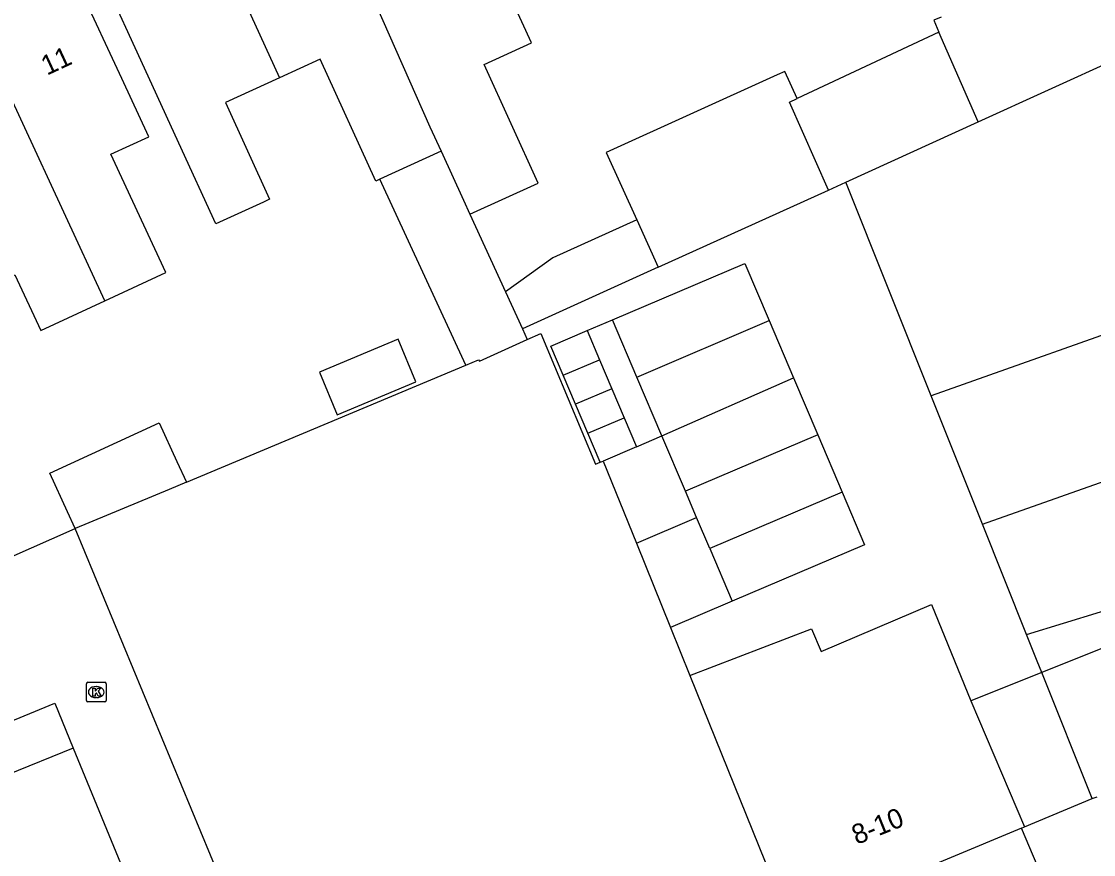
# Model space of a CAD drawing. Extents: x 160379 to 161131, y 383940 to 384849.
# Drawn here: x 161040.9 to 161095.3, y 384292.9 to 384335.2 of the extents above; entities that cross this region are included whole.
import ezdxf

# ---------------------------------------------------------------- set-up
doc = ezdxf.new("R2010")
doc.units = 0
for name, color, linetype in [('IMGEO_Kolk', 7, 'Continuous'), ('IMGEO_Muur', 7, 'Continuous'), ('IMGEO_Pand', 7, 'Continuous'), ('IMGEO_Pand_nummerreeks', 7, 'Continuous'), ('IMGEO_Pand_overbouw', 7, 'Continuous'), ('IMGEO_Voetpad_open', 7, 'Continuous')]:
    doc.layers.add(name, color=color, linetype=linetype)

msp = doc.modelspace()

# ---------------------------------------------------------------- linework, layer by layer
at = {"layer": 'IMGEO_Kolk'}
for p, q in [((161044.21, 384300.753), (161044.21, 384301.605)), ((161044.285, 384301.679), (161045.137, 384301.679)), ((161044.698, 384301.459), (161044.723, 384301.459)), ((161045.211, 384301.605), (161045.211, 384300.753)), ((161045.137, 384300.679), (161044.285, 384300.679)), ((161044.721, 384300.899), (161044.696, 384300.899))]:
    msp.add_line(p, q, dxfattribs=at)
for points in [[(161044.21, 384300.753), (161044.21, 384301.605)], [(161044.285, 384301.679), (161045.137, 384301.679)], [(161044.531, 384301.379), (161044.654, 384301.379), (161044.654, 384301.228), (161044.784, 384301.379), (161044.948, 384301.379), (161044.802, 384301.228), (161044.955, 384300.979), (161044.803, 384300.979), (161044.718, 384301.143), (161044.654, 384301.076), (161044.654, 384300.979), (161044.531, 384300.979), (161044.531, 384301.379)], [(161045.211, 384301.605), (161045.211, 384300.753)], [(161045.137, 384300.679), (161044.285, 384300.679)]]:
    msp.add_lwpolyline(points, dxfattribs=at)
for centre, start, end in [((161044.287, 384301.603), 91.552, 178.448), ((161044.287, 384301.603), 91.552, 178.448), ((161045.135, 384301.603), 1.552, 88.448), ((161045.135, 384301.603), 1.552, 88.448), ((161044.287, 384300.755), 181.552, 268.448), ((161044.287, 384300.755), 181.552, 268.448), ((161045.135, 384300.755), 271.552, 358.448), ((161045.135, 384300.755), 271.552, 358.448)]:
    msp.add_arc(centre, 0.0765, start, end, dxfattribs=at)
for centre, major_axis, ratio, start_param, end_param in [((161044.697, 384301.179), (-0.387, 0.002), 0.722429, 4.712389, 7.853982), ((161044.722, 384301.179), (-0.39, 0.002), 0.717154, 1.570796, 4.712389)]:
    msp.add_ellipse(centre, major_axis=major_axis, ratio=ratio, start_param=start_param, end_param=end_param, dxfattribs=at)
at = {"layer": 'IMGEO_Muur'}
for points in [[(161031.058, 384303.917), (161043.635, 384309.473)], [(161043.533, 384298.344), (161046.299, 384291.649)]]:
    msp.add_lwpolyline(points, dxfattribs=at)
at = {"layer": 'IMGEO_Pand'}
for points in [[(161063.67, 384325.406), (161067.13, 384326.989), (161064.382, 384332.994), (161066.784, 384334.093), (161063.869, 384340.464), (161061.789, 384345.01)], [(161056.087, 384342.401), (161061.638, 384329.845), (161062.208, 384328.6)], [(161050.558, 384339.871), (161054.008, 384332.328)], [(161054.008, 384332.328), (161051.263, 384331.072), (161053.506, 384326.171), (161053.189, 384326.026), (161050.771, 384324.923), (161048.898, 384329.016), (161047.159, 384332.817), (161045.078, 384337.363)], [(161045.14, 384321.014), (161048.232, 384322.45), (161045.449, 384328.444), (161047.376, 384329.338), (161046.004, 384332.293), (161043.899, 384336.828)], [(161087.571, 384335.404), (161087.199, 384335.247), (161087.465, 384334.636)], [(161089.448, 384330.086), (161100.161, 384334.957)], [(161045.14, 384321.014), (161038.881, 384334.499)], [(161087.465, 384334.636), (161080.266, 384331.274)], [(161089.448, 384330.086), (161087.465, 384334.636)], [(161059.102, 384327.179), (161058.895, 384327.084), (161056.065, 384333.269), (161054.008, 384332.328)], [(161080.266, 384331.274), (161079.641, 384332.65), (161079.259, 384332.477), (161070.584, 384328.541), (161072.132, 384325.129)], [(161033.861, 384332.169), (161035.966, 384327.634), (161037.783, 384323.72), (161038.808, 384321.512), (161040.584, 384322.337), (161041.897, 384319.509), (161045.14, 384321.014)], [(161081.851, 384326.634), (161079.874, 384331.091), (161080.266, 384331.274)], [(161082.731, 384327.033), (161089.448, 384330.086)], [(161062.208, 384328.6), (161059.102, 384327.179)], [(161062.208, 384328.6), (161063.341, 384326.125), (161063.67, 384325.406)], [(161063.456, 384317.756), (161059.102, 384327.179)], [(161081.851, 384326.634), (161082.731, 384327.033)], [(161087.066, 384316.202), (161082.731, 384327.033)], [(161073.225, 384322.72), (161081.851, 384326.634)], [(161063.67, 384325.406), (161065.468, 384321.479)], [(161072.132, 384325.129), (161067.868, 384323.194), (161065.468, 384321.479)], [(161072.132, 384325.129), (161073.225, 384322.72)], [(161111.312, 384324.78), (161087.066, 384316.202)], [(161073.225, 384322.72), (161066.332, 384319.592)], [(161070.9, 384320.053), (161077.616, 384322.912), (161078.85, 384320.013)], [(161065.468, 384321.479), (161066.332, 384319.592)], [(161069.611, 384319.504), (161070.9, 384320.053)], [(161072.133, 384317.154), (161070.9, 384320.053)], [(161072.133, 384317.154), (161078.85, 384320.013)], [(161078.85, 384320.013), (161080.084, 384317.115)], [(161066.332, 384319.592), (161066.575, 384319.061)], [(161066.575, 384319.061), (161067.27, 384319.352), (161070.04, 384312.733), (161070.278, 384312.832)], [(161068.398, 384317.249), (161067.771, 384318.721), (161069.611, 384319.504)], [(161069.611, 384319.504), (161070.238, 384318.032)], [(161056.035, 384317.395), (161056.938, 384315.237), (161060.928, 384316.907), (161060.025, 384319.065), (161056.035, 384317.395)], [(161063.456, 384317.756), (161064.108, 384318.029), (161064.145, 384317.949), (161066.575, 384319.061)], [(161089.673, 384309.688), (161105.562, 384315.309), (161113.537, 384318.13)], [(161049.287, 384311.826), (161063.456, 384317.756)], [(161068.398, 384317.249), (161070.238, 384318.032)], [(161070.238, 384318.032), (161070.865, 384316.56)], [(161069.024, 384315.777), (161068.398, 384317.249)], [(161073.406, 384314.164), (161072.133, 384317.154)], [(161073.406, 384314.164), (161080.084, 384317.115)], [(161080.084, 384317.115), (161081.317, 384314.216)], [(161070.865, 384316.56), (161069.024, 384315.777)], [(161070.865, 384316.56), (161071.491, 384315.088)], [(161089.673, 384309.688), (161087.066, 384316.202)], [(161069.651, 384314.305), (161069.024, 384315.777)], [(161043.635, 384309.473), (161043.256, 384310.316), (161042.353, 384312.273), (161047.899, 384314.834), (161048.802, 384312.878), (161049.287, 384311.826)], [(161069.651, 384314.305), (161071.491, 384315.088)], [(161071.491, 384315.088), (161072.118, 384313.616)], [(161070.278, 384312.832), (161069.651, 384314.305)], [(161072.118, 384313.616), (161073.406, 384314.164)], [(161074.6, 384311.358), (161073.406, 384314.164)], [(161081.317, 384314.216), (161074.6, 384311.358)], [(161081.317, 384314.216), (161082.551, 384311.318)], [(161072.118, 384313.616), (161070.425, 384312.894)], [(161070.278, 384312.832), (161070.425, 384312.894)], [(161070.425, 384312.894), (161072.112, 384308.722)], [(161049.287, 384311.826), (161048.407, 384311.458), (161043.635, 384309.473)], [(161075.168, 384310.023), (161074.6, 384311.358)], [(161082.551, 384311.318), (161075.834, 384308.459)], [(161082.551, 384311.318), (161083.687, 384308.65), (161076.97, 384305.791)], [(161091.912, 384304.095), (161105.038, 384308.129), (161115.758, 384311.423)], [(161072.112, 384308.722), (161075.168, 384310.023)], [(161075.834, 384308.459), (161075.168, 384310.023)], [(161056.088, 384279.458), (161052.467, 384288.186), (161043.635, 384309.473)], [(161091.912, 384304.095), (161089.673, 384309.688)], [(161072.112, 384308.722), (161073.837, 384304.457)], [(161075.834, 384308.459), (161076.97, 384305.791)], [(161076.97, 384305.791), (161073.837, 384304.457)], [(161074.82, 384302.027), (161081.001, 384304.385), (161081.491, 384303.235), (161087.091, 384305.618), (161089.077, 384300.732), (161091.796, 384294.344)], [(161102.532, 384298.699), (161099.976, 384305.092), (161096.435, 384303.676), (161092.681, 384302.175)], [(161073.837, 384304.457), (161074.82, 384302.027)], [(161092.681, 384302.175), (161092.449, 384302.755), (161091.912, 384304.095)], [(161074.82, 384302.027), (161079.928, 384289.396)], [(161095.241, 384295.78), (161092.681, 384302.175)], [(161042.604, 384300.613), (161043.533, 384298.344), (161040.213, 384296.985), (161039.283, 384299.248), (161042.604, 384300.613)], [(161095.241, 384295.78), (161095.484, 384295.877)], [(161091.647, 384294.282), (161079.928, 384289.396)], [(161091.647, 384294.282), (161091.796, 384294.344)]]:
    msp.add_lwpolyline(points, dxfattribs=at)
at = {"layer": 'IMGEO_Pand_overbouw'}
msp.add_lwpolyline([(161095.241, 384295.78), (161092.681, 384302.175), (161089.077, 384300.732), (161091.796, 384294.344)], close=True, dxfattribs=at)
at = {"layer": 'IMGEO_Voetpad_open'}
for points in [[(161091.796, 384294.344), (161095.241, 384295.78)], [(161092.869, 384291.413), (161091.647, 384294.282)]]:
    msp.add_lwpolyline(points, dxfattribs=at)

# ---------------------------------------------------------------- texts
at = {"layer": 'IMGEO_Pand_nummerreeks'}
for s, rotation, p in [('11', 24.8977, (161042.206, 384332.427)), ('8-10', 22.0155, (161083.291, 384293.425))]:
    msp.add_text(s, height=1, rotation=rotation, dxfattribs=at).set_placement(p)

doc.saveas('drawing.dxf')
